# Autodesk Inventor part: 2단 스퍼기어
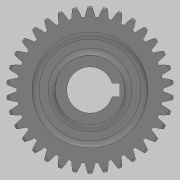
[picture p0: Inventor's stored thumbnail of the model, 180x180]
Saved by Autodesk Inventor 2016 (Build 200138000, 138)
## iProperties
Created: 2018-09
Part Number: 2단 스퍼기어
Material: 스테인레스 스틸
Document SubType Name: Modeling
Designer: MYS
Mass: 384.368 g
Surface Area: 216.091 cm^2
Volume: 48.0459 cm^3
Density: 8 g/cm^3
Appearance: 반연마
Author: MYS
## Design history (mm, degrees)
sketch "스케치1"
  geometry: L1 (0, 0)-(47, 0); L2 (47, 0)-(47, 15); L3 (47, 15)-(0, 15); L4 (0, 15)-(0, 0); L5 (14, 0)-(24, 0); L6 (24, 0)-(24, 36); L7 (24, 36)-(14, 36); L8 (14, 36)-(14, 0); L9 (47, 0)-(37, 0); L10 (37, 0)-(37, 24); L11 (37, 24)-(47, 24); L12 (47, 24)-(47, 0)
  constraints: 24 end point, 6 parallel, 3 horizontal, 3 perpendicular, 1 point on line
  dimensions: "d0" = 47 distance between parallel lines of L2 L4; "d1" = 14 distance between parallel lines of L4 L8; "d2" = 10 distance of L6.end L7.end; "d3" = 10 distance of L10.end L11.end; "d4" = 13 distance between parallel lines of L10 L6 (derived); "d5" = 72 diameter of L7 L1; "d6" = 48 diameter of L11 L1; "d7" = 30 diameter of L3 L1
revolve "회전1" sketch "스케치1" stored, may be unused: angle "d8" = 90 deg
sketch "스케치2"
  geometry: C1 r 25 at (0, 0); C2 r 15 at (0, 0); 1 further point
  constraints: 2 centre point, 2 coincident
  dimensions: "d9" = 50 diameter of C1; "d10" = 30 diameter of C2
extrude "돌출1" cut sketch "스케치2" distance "d11" = 3; taper "d12" = 0 deg
sketch "스케치3"
  geometry: C1 r 25 at (0, 0); C2 r 15 at (0, 0); 1 further point
  constraints: 2 centre point, 2 coincident
  dimensions: "d13" = 50 diameter of C1; "d14" = 30 diameter of C2
extrude "돌출2" cut sketch "스케치3" distance "d15" = 3; taper "d16" = 0 deg
chamfer "모따기2" distance "d35" = 1; stored, may be unused: second distance "d36" = 2, angle "d37" = 45 deg
node "스퍼 기어 톱니1"
node "스퍼 기어 톱니2"
sketch "스케치5"
  geometry: L1 (-3, 12.8)-(3, 12.8); L2 (3, 12.8)-(3, 0); L3 (3, 0)-(-3, 0); L4 (-3, 0)-(-3, 12.8); C1 r 10 at (0, 0); 2 further points
  constraints: 8 end point, 2 coincident, 2 parallel, 1 centre point, 1 horizontal, 1 midpoint, 1 perpendicular
  dimensions: "d38" = 20 diameter of C1; "d39" = 6 distance of L1.start L1.end; "d40" = 22.8 dimension on C1 L1
extrude "돌출4" cut sketch "스케치5" stored distance "d41" = 10; taper "d42" = 0 deg
fillet "모깎기5" dims "d43" = 3
fillet "모깎기6" dims "d44" = 2
node "솔리드1"
feature "스퍼 기어1"
feature "스퍼 기어12"
